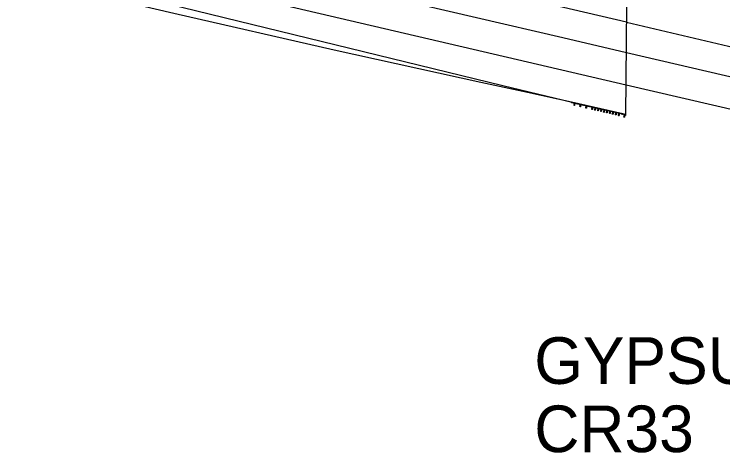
# Model space of a CAD drawing. Extents: x 1855721 to 1876784, y 662259 to 674089.
# Drawn here: x 1866661.7 to 1866935, y 670573.2 to 670742.4 of the extents above; entities that cross this region are included whole.
import ezdxf

# ---------------------------------------------------------------- set-up
doc = ezdxf.new("R2010")
doc.units = 0
for name, color, linetype in [('_CIVIL_CONSTRUCTION', 7, 'Continuous'), ('GE_X_Alignment_100_Bearings', 7, 'Continuous'), ('GE_X_Alignment_100_Curve_Data', 7, 'Continuous'), ('RD_P_GR_Lt', 7, 'Continuous'), ('SC_Scratch1', 7, 'Continuous'), ('ST_Details', 7, 'Continuous')]:
    doc.layers.add(name, color=color, linetype=linetype)

msp = doc.modelspace()

# ---------------------------------------------------------------- linework, layer by layer
at = {"layer": '_CIVIL_CONSTRUCTION'}
msp.add_line((1866897.85, 670745.57), (1866897.46, 670703.32), dxfattribs=at)
msp.add_lwpolyline([(1861013.57, 672092.03), (1861415.75, 671997.75), (1861745.02, 671920.85), (1861896.09, 671885.62), (1862012.27, 671858.53), (1862412.28, 671765.18), (1862742.48, 671687.92), (1862966.47, 671635.34), (1863245.1, 671569.98), (1863477.55, 671515.73), (1863735.03, 671455.32), (1863965.71, 671401.1), (1864326.72, 671316.71), (1864597.34, 671253.4), (1865050.25, 671147.36), (1865653.59, 671006.7), (1866010.66, 670923.03), (1866378.51, 670836.48), (1866645.32, 670774.11), (1866897.69, 670715.1)], dxfattribs=at)
at = {"layer": 'GE_X_Alignment_100_Bearings'}
msp.add_lwpolyline([(1861015.79, 672104.14), (1861503.86, 671989.83), (1862002.3, 671873.34), (1862414.38, 671777.36), (1862607.45, 671732.41), (1862665.93, 671718.29), (1862877.58, 671669), (1863214.23, 671589.72), (1863466.96, 671530.76), (1863729.81, 671469.09), (1863993.06, 671407.41), (1864487.85, 671291.8), (1864979.89, 671176.39), (1865473.4, 671061.63), (1866013.64, 670934.86), (1866351.37, 670855.59), (1866552.5, 670808.76), (1866760.09, 670759.75), (1866873.31, 670733.34), (1866897.79, 670727.56), (1867013.17, 670700.87)], dxfattribs=at)
at = {"layer": 'GE_X_Alignment_100_Curve_Data'}
for p, q in [((1866897.79, 670739.26), (1867013.1, 670712.33)), ((1866897.69, 670715.1), (1867012.95, 670688.28))]:
    msp.add_line(p, q, dxfattribs=at)
msp.add_lwpolyline([(1866897.79, 670739.26), (1866770.4, 670769.26), (1866633.99, 670801.24), (1866314.99, 670876.12), (1866186.79, 670906.2), (1865771.3, 671003.48), (1865284.25, 671117.24), (1864960.57, 671192.76), (1864427.03, 671317.77), (1864078.73, 671399.21), (1863649.61, 671499.8), (1863334.6, 671573.5), (1862712.87, 671719.11), (1862434.48, 671784.11), (1861947.09, 671897.98), (1861710.56, 671953.19), (1861378.66, 672030.79), (1861046.07, 672108.75)], dxfattribs=at)
at = {"layer": 'RD_P_GR_Lt'}
msp.add_lwpolyline([(1866876.69, 670708.41), (1866859.66, 670712.16), (1866841.64, 670716.05), (1866785.04, 670728.5), (1866723.29, 670742.62), (1866648.5, 670760.18), (1866499.74, 670794.82), (1866250.04, 670854.29), (1866058.6, 670899.37)], dxfattribs=at)
at = {"layer": 'SC_Scratch1'}
msp.add_lwpolyline([(1866897.42, 670703.5), (1866883.77, 670706.63), (1866850.17, 670714.75), (1866715.74, 670747.46), (1866529.4, 670790.93), (1866335.12, 670836.62), (1866154.72, 670878.95), (1865908, 670936.81), (1865807.98, 670960.25), (1865622.8, 671003.65), (1865282.61, 671083.17), (1864786.67, 671198.92), (1864250.64, 671324.25), (1863882.8, 671410.43), (1863380.3, 671528.31), (1862865.34, 671648.88), (1862542.41, 671724.73), (1862131.5, 671820.55), (1861446.39, 671980.7), (1861012.14, 672082.41)], dxfattribs=at)
at = {"layer": 'ST_Details'}
for p, q in [((1866897.49, 670703.49), (1866876.64, 670708.2)), ((1866896.48, 670703.93), (1866876.69, 670708.41)), ((1866877.49, 670708.23), (1866877.44, 670708.02)), ((1866877.65, 670707.97), (1866877.48, 670707.24)), ((1866877.51, 670707.23), (1866877.49, 670707.23)), ((1866877.52, 670707.24), (1866877.51, 670707.23)), ((1866877.78, 670707.18), (1866877.52, 670707.24)), ((1866877.97, 670707.9), (1866877.65, 670707.97)), ((1866877.66, 670707.2), (1866877.66, 670707.19)), ((1866877.78, 670707.16), (1866877.66, 670707.19)), ((1866877.68, 670707.11), (1866877.7, 670707.2)), ((1866877.68, 670707.18), (1866877.68, 670707.14)), ((1866877.74, 670707.12), (1866877.68, 670707.13)), ((1866877.73, 670707.1), (1866877.68, 670707.11)), ((1866877.86, 670707.93), (1866877.7, 670707.2)), ((1866877.73, 670707.1), (1866877.75, 670707.19)), ((1866877.91, 670707.92), (1866877.75, 670707.19)), ((1866877.76, 670707.16), (1866877.75, 670707.13)), ((1866877.78, 670707.18), (1866877.78, 670707.17)), ((1866877.78, 670707.17), (1866877.78, 670707.16)), ((1866877.81, 670707.16), (1866877.78, 670707.17)), ((1866877.98, 670707.89), (1866877.82, 670707.17)), ((1866878.25, 670708.05), (1866878.2, 670707.85)), ((1866879.93, 670707.45), (1866879.77, 670706.72)), ((1866879.8, 670706.71), (1866879.77, 670706.71)), ((1866879.8, 670706.73), (1866879.8, 670706.71)), ((1866880.07, 670706.67), (1866879.8, 670706.73)), ((1866880.26, 670707.38), (1866879.94, 670707.46)), ((1866879.95, 670706.68), (1866879.95, 670706.67)), ((1866880.06, 670706.64), (1866879.95, 670706.67)), ((1866879.97, 670706.66), (1866879.96, 670706.63)), ((1866879.97, 670706.59), (1866879.99, 670706.68)), ((1866880.02, 670706.6), (1866879.97, 670706.62)), ((1866880.01, 670706.58), (1866879.97, 670706.59)), ((1866880.15, 670707.41), (1866879.99, 670706.68)), ((1866880.01, 670706.58), (1866880.03, 670706.67)), ((1866880.2, 670707.4), (1866880.03, 670706.67)), ((1866880.04, 670706.65), (1866880.03, 670706.61)), ((1866880.07, 670706.67), (1866880.06, 670706.65)), ((1866880.06, 670706.65), (1866880.06, 670706.64)), ((1866880.09, 670706.64), (1866880.06, 670706.65)), ((1866880.27, 670707.37), (1866880.1, 670706.65)), ((1866882.07, 670707.19), (1866882.03, 670706.98)), ((1866882.22, 670706.93), (1866882.05, 670706.21)), ((1866882.09, 670706.19), (1866882.06, 670706.2)), ((1866882.09, 670706.21), (1866882.09, 670706.19)), ((1866882.35, 670706.15), (1866882.09, 670706.21)), ((1866882.55, 670706.87), (1866882.23, 670706.94)), ((1866882.24, 670706.16), (1866882.23, 670706.15)), ((1866882.35, 670706.13), (1866882.23, 670706.15)), ((1866882.25, 670706.08), (1866882.27, 670706.17)), ((1866882.44, 670706.89), (1866882.27, 670706.17)), ((1866882.3, 670706.07), (1866882.32, 670706.16)), ((1866882.48, 670706.88), (1866882.32, 670706.16)), ((1866882.55, 670706.86), (1866882.39, 670706.13)), ((1866882.84, 670707.02), (1866882.79, 670706.81)), ((1866884.5, 670706.42), (1866884.34, 670705.69)), ((1866884.83, 670706.35), (1866884.51, 670706.42)), ((1866884.72, 670706.37), (1866884.56, 670705.65)), ((1866884.77, 670706.36), (1866884.6, 670705.64)), ((1866884.84, 670706.34), (1866884.67, 670705.61)), ((1866885.65, 670706.16), (1866885.48, 670705.43)), ((1866885.98, 670706.09), (1866885.66, 670706.16)), ((1866886.59, 670705.95), (1866886.64, 670706.16)), ((1866882.26, 670706.15), (1866882.25, 670706.11)), ((1866882.31, 670706.09), (1866882.25, 670706.1)), ((1866882.3, 670706.07), (1866882.25, 670706.08)), ((1866882.33, 670706.13), (1866882.32, 670706.09)), ((1866882.35, 670706.15), (1866882.35, 670706.13)), ((1866882.35, 670706.14), (1866882.35, 670706.13)), ((1866882.38, 670706.13), (1866882.35, 670706.13)), ((1866884.37, 670705.67), (1866884.34, 670705.68)), ((1866884.38, 670705.69), (1866884.37, 670705.67)), ((1866884.64, 670705.63), (1866884.38, 670705.69)), ((1866884.52, 670705.64), (1866884.52, 670705.63)), ((1866884.63, 670705.61), (1866884.52, 670705.63)), ((1866884.54, 670705.63), (1866884.53, 670705.59)), ((1866884.54, 670705.56), (1866884.56, 670705.65)), ((1866884.59, 670705.57), (1866884.54, 670705.58)), ((1866884.58, 670705.55), (1866884.54, 670705.56)), ((1866884.58, 670705.55), (1866884.6, 670705.64)), ((1866884.61, 670705.61), (1866884.6, 670705.58)), ((1866884.64, 670705.62), (1866884.63, 670705.61)), ((1866884.64, 670705.63), (1866884.64, 670705.61)), ((1866884.67, 670705.61), (1866884.64, 670705.61)), ((1866885.52, 670705.42), (1866885.49, 670705.42)), ((1866885.52, 670705.43), (1866885.52, 670705.42)), ((1866885.78, 670705.37), (1866885.52, 670705.43)), ((1866885.67, 670705.39), (1866885.66, 670705.38)), ((1866885.78, 670705.35), (1866885.66, 670705.38)), ((1866885.68, 670705.3), (1866885.7, 670705.39)), ((1866885.68, 670705.37), (1866885.68, 670705.33)), ((1866885.74, 670705.31), (1866885.68, 670705.32)), ((1866885.73, 670705.29), (1866885.68, 670705.3)), ((1866885.86, 670706.12), (1866885.7, 670705.39)), ((1866885.73, 670705.29), (1866885.75, 670705.38)), ((1866885.91, 670706.11), (1866885.75, 670705.38)), ((1866885.76, 670705.35), (1866885.75, 670705.32)), ((1866885.78, 670705.37), (1866885.78, 670705.36)), ((1866885.78, 670705.36), (1866885.78, 670705.35)), ((1866885.81, 670705.35), (1866885.78, 670705.36)), ((1866885.98, 670706.08), (1866885.82, 670705.35)), ((1866886.79, 670705.9), (1866886.62, 670705.17)), ((1866886.66, 670705.16), (1866886.63, 670705.16)), ((1866886.66, 670705.17), (1866886.66, 670705.16)), ((1866886.93, 670705.11), (1866886.66, 670705.17)), ((1866887.12, 670705.83), (1866886.8, 670705.9)), ((1866886.81, 670705.13), (1866886.81, 670705.12)), ((1866886.92, 670705.09), (1866886.81, 670705.12)), ((1866886.82, 670705.04), (1866886.84, 670705.13)), ((1866886.83, 670705.11), (1866886.82, 670705.08)), ((1866886.88, 670705.05), (1866886.82, 670705.06)), ((1866886.87, 670705.03), (1866886.82, 670705.04)), ((1866887.01, 670705.86), (1866886.84, 670705.13)), ((1866886.87, 670705.03), (1866886.89, 670705.12)), ((1866887.05, 670705.85), (1866886.89, 670705.12)), ((1866886.9, 670705.1), (1866886.89, 670705.06)), ((1866886.93, 670705.11), (1866886.92, 670705.1)), ((1866886.92, 670705.1), (1866886.92, 670705.09)), ((1866886.95, 670705.09), (1866886.92, 670705.1)), ((1866887.12, 670705.82), (1866886.96, 670705.1)), ((1866887.32, 670705.79), (1866887.37, 670705.99)), ((1866887.93, 670705.64), (1866887.77, 670704.91)), ((1866887.8, 670704.9), (1866887.77, 670704.9)), ((1866887.81, 670704.92), (1866887.8, 670704.9)), ((1866888.07, 670704.86), (1866887.81, 670704.92)), ((1866888.26, 670705.57), (1866887.94, 670705.65)), ((1866887.95, 670704.87), (1866887.95, 670704.86)), ((1866888.06, 670704.83), (1866887.95, 670704.86)), ((1866887.97, 670704.85), (1866887.96, 670704.82)), ((1866887.97, 670704.78), (1866887.99, 670704.87)), ((1866888.02, 670704.79), (1866887.97, 670704.81)), ((1866888.01, 670704.77), (1866887.97, 670704.78)), ((1866888.15, 670705.6), (1866887.99, 670704.87)), ((1866888.01, 670704.77), (1866888.03, 670704.86)), ((1866888.2, 670705.59), (1866888.03, 670704.86)), ((1866888.04, 670704.84), (1866888.03, 670704.8)), ((1866888.07, 670704.84), (1866888.06, 670704.83)), ((1866888.07, 670704.86), (1866888.07, 670704.84)), ((1866888.09, 670704.83), (1866888.07, 670704.84)), ((1866888.27, 670705.56), (1866888.1, 670704.84)), ((1866889.08, 670705.38), (1866888.91, 670704.66)), ((1866888.94, 670704.64), (1866888.92, 670704.65)), ((1866888.95, 670704.66), (1866888.94, 670704.64)), ((1866889.21, 670704.6), (1866888.95, 670704.66)), ((1866889.4, 670705.31), (1866889.08, 670705.39)), ((1866889.09, 670704.61), (1866889.09, 670704.6)), ((1866889.21, 670704.57), (1866889.09, 670704.6)), ((1866889.11, 670704.59), (1866889.1, 670704.56)), ((1866889.11, 670704.52), (1866889.13, 670704.62)), ((1866889.17, 670704.53), (1866889.11, 670704.55)), ((1866889.16, 670704.51), (1866889.11, 670704.52)), ((1866889.29, 670705.34), (1866889.13, 670704.62)), ((1866889.16, 670704.51), (1866889.18, 670704.61)), ((1866889.34, 670705.33), (1866889.18, 670704.61)), ((1866889.18, 670704.58), (1866889.18, 670704.54)), ((1866889.21, 670704.6), (1866889.21, 670704.58)), ((1866889.21, 670704.58), (1866889.21, 670704.57)), ((1866889.24, 670704.57), (1866889.21, 670704.58)), ((1866889.41, 670705.31), (1866889.25, 670704.58)), ((1866890.22, 670705.12), (1866890.05, 670704.4)), ((1866890.09, 670704.38), (1866890.06, 670704.39)), ((1866890.09, 670704.4), (1866890.09, 670704.38)), ((1866890.36, 670704.34), (1866890.09, 670704.4)), ((1866890.55, 670705.06), (1866890.23, 670705.13)), ((1866890.24, 670704.35), (1866890.23, 670704.34)), ((1866890.35, 670704.31), (1866890.23, 670704.34)), ((1866890.25, 670704.27), (1866890.27, 670704.36)), ((1866890.26, 670704.34), (1866890.25, 670704.3)), ((1866890.31, 670704.28), (1866890.25, 670704.29)), ((1866890.3, 670704.26), (1866890.25, 670704.27)), ((1866890.44, 670705.08), (1866890.27, 670704.36)), ((1866890.3, 670704.26), (1866890.32, 670704.35)), ((1866890.48, 670705.07), (1866890.32, 670704.35)), ((1866890.33, 670704.32), (1866890.32, 670704.28)), ((1866890.36, 670704.34), (1866890.35, 670704.32)), ((1866890.35, 670704.33), (1866890.35, 670704.31)), ((1866890.38, 670704.31), (1866890.35, 670704.32)), ((1866890.55, 670705.05), (1866890.39, 670704.32)), ((1866891.36, 670704.86), (1866891.2, 670704.14)), ((1866891.23, 670704.12), (1866891.2, 670704.13)), ((1866891.23, 670704.14), (1866891.23, 670704.12)), ((1866891.5, 670704.08), (1866891.23, 670704.14)), ((1866891.69, 670704.8), (1866891.37, 670704.87)), ((1866891.38, 670704.09), (1866891.38, 670704.08)), ((1866891.49, 670704.06), (1866891.38, 670704.08)), ((1866891.4, 670704.08), (1866891.39, 670704.04)), ((1866891.4, 670704.01), (1866891.42, 670704.1)), ((1866891.45, 670704.02), (1866891.4, 670704.03)), ((1866891.44, 670704), (1866891.4, 670704.01)), ((1866891.58, 670704.82), (1866891.42, 670704.1)), ((1866891.44, 670704), (1866891.46, 670704.09)), ((1866891.63, 670704.81), (1866891.46, 670704.09)), ((1866891.47, 670704.06), (1866891.46, 670704.02)), ((1866891.5, 670704.08), (1866891.49, 670704.06)), ((1866891.49, 670704.07), (1866891.49, 670704.06)), ((1866891.52, 670704.06), (1866891.49, 670704.06)), ((1866891.7, 670704.79), (1866891.53, 670704.06)), ((1866892.5, 670704.61), (1866892.34, 670703.88)), ((1866892.37, 670703.86), (1866892.35, 670703.87)), ((1866892.38, 670703.88), (1866892.37, 670703.86)), ((1866892.64, 670703.82), (1866892.38, 670703.88)), ((1866892.83, 670704.54), (1866892.51, 670704.61)), ((1866892.52, 670703.83), (1866892.52, 670703.82)), ((1866892.63, 670703.8), (1866892.52, 670703.82)), ((1866892.54, 670703.82), (1866892.53, 670703.78)), ((1866892.54, 670703.75), (1866892.56, 670703.84)), ((1866892.6, 670703.76), (1866892.54, 670703.77)), ((1866892.58, 670703.74), (1866892.54, 670703.75)), ((1866892.72, 670704.56), (1866892.56, 670703.84)), ((1866892.58, 670703.74), (1866892.6, 670703.83)), ((1866892.77, 670704.55), (1866892.6, 670703.83)), ((1866892.61, 670703.8), (1866892.61, 670703.77)), ((1866892.64, 670703.81), (1866892.63, 670703.8)), ((1866892.64, 670703.82), (1866892.64, 670703.8)), ((1866892.67, 670703.8), (1866892.64, 670703.8)), ((1866892.84, 670704.53), (1866892.68, 670703.8)), ((1866893.65, 670704.35), (1866893.48, 670703.62)), ((1866893.52, 670703.61), (1866893.49, 670703.61)), ((1866893.52, 670703.62), (1866893.52, 670703.61)), ((1866893.78, 670703.56), (1866893.52, 670703.62)), ((1866893.98, 670704.28), (1866893.66, 670704.35)), ((1866893.67, 670703.58), (1866893.66, 670703.57)), ((1866893.78, 670703.54), (1866893.66, 670703.57)), ((1866893.68, 670703.49), (1866893.7, 670703.58)), ((1866893.69, 670703.56), (1866893.68, 670703.52)), ((1866893.74, 670703.5), (1866893.68, 670703.51)), ((1866893.73, 670703.48), (1866893.68, 670703.49)), ((1866893.87, 670704.31), (1866893.7, 670703.58)), ((1866893.73, 670703.48), (1866893.75, 670703.57)), ((1866893.91, 670704.29), (1866893.75, 670703.57)), ((1866893.76, 670703.54), (1866893.75, 670703.51)), ((1866893.78, 670703.56), (1866893.78, 670703.55)), ((1866893.78, 670703.55), (1866893.78, 670703.54)), ((1866893.81, 670703.54), (1866893.78, 670703.55)), ((1866893.98, 670704.27), (1866893.82, 670703.54)), ((1866894.79, 670704.09), (1866894.63, 670703.36)), ((1866895.12, 670704.02), (1866894.8, 670704.09)), ((1866895.01, 670704.05), (1866894.85, 670703.32)), ((1866895.05, 670704.04), (1866894.89, 670703.31)), ((1866895.13, 670704.01), (1866894.96, 670703.29)), ((1866895.66, 670703.9), (1866895.71, 670704.1)), ((1866895.75, 670704.09), (1866895.71, 670703.89)), ((1866896.48, 670703.71), (1866896.53, 670703.92)), ((1866896.86, 670702.69), (1866897.06, 670703.58)), ((1866896.92, 670702.68), (1866897.13, 670703.57)), ((1866897.09, 670702.64), (1866897.29, 670703.53)), ((1866897.16, 670702.62), (1866897.36, 670703.51)), ((1866897.49, 670703.49), (1866897.38, 670703.52)), ((1866897.42, 670703.5), (1866897.42, 670703.51)), ((1866897.42, 670703.5), (1866897.42, 670703.5)), ((1866894.66, 670703.35), (1866894.63, 670703.35)), ((1866894.66, 670703.36), (1866894.66, 670703.35)), ((1866894.93, 670703.3), (1866894.66, 670703.36)), ((1866894.81, 670703.32), (1866894.81, 670703.31)), ((1866894.92, 670703.28), (1866894.81, 670703.31)), ((1866894.82, 670703.23), (1866894.85, 670703.32)), ((1866894.83, 670703.3), (1866894.82, 670703.27)), ((1866894.88, 670703.24), (1866894.82, 670703.25)), ((1866894.87, 670703.22), (1866894.82, 670703.23)), ((1866894.87, 670703.22), (1866894.89, 670703.31)), ((1866894.9, 670703.29), (1866894.89, 670703.25)), ((1866894.93, 670703.3), (1866894.92, 670703.29)), ((1866894.92, 670703.29), (1866894.92, 670703.28)), ((1866894.95, 670703.28), (1866894.92, 670703.29)), ((1866897.16, 670702.62), (1866896.86, 670702.69))]:
    msp.add_line(p, q, dxfattribs=at)
for points in [[(1866876.64, 670708.2), (1866876.65, 670708.28), (1866876.65, 670708.28), (1866876.69, 670708.41)], [(1866897.14, 670703.56), (1866897.16, 670703.62), (1866897.05, 670703.64), (1866897.04, 670703.59)], [(1866897.38, 670703.52), (1866897.39, 670703.56), (1866897.29, 670703.59), (1866897.28, 670703.54)]]:
    msp.add_lwpolyline(points, dxfattribs=at)
for centre, radius, start, end in [((1866877.49, 670707.24), 0.0075, 167.2516, 257.2516), ((1866877.65, 670707.97), 0.0075, 77.2516, 167.2516), ((1866877.81, 670707.17), 0.0075, 257.2516, 347.2516), ((1866877.97, 670707.89), 0.0075, 347.2516, 77.2516), ((1866879.77, 670706.72), 0.0075, 167.2516, 257.2516), ((1866879.94, 670707.45), 0.0075, 77.2516, 167.2516), ((1866880.09, 670706.65), 0.0075, 257.2516, 347.2516), ((1866880.26, 670707.38), 0.0075, 347.2516, 77.2516), ((1866882.06, 670706.2), 0.0075, 167.2516, 257.2516), ((1866882.22, 670706.93), 0.0075, 77.2516, 167.2516), ((1866882.55, 670706.86), 0.0075, 347.2516, 77.2516), ((1866884.51, 670706.41), 0.0075, 77.2516, 167.2516), ((1866884.83, 670706.34), 0.0075, 347.2516, 77.2516), ((1866885.65, 670706.16), 0.0075, 77.2516, 167.2516), ((1866882.38, 670706.13), 0.0075, 257.2516, 347.2516), ((1866884.35, 670705.69), 0.0075, 167.2516, 257.2516), ((1866884.67, 670705.62), 0.0075, 257.2516, 347.2516), ((1866885.49, 670705.43), 0.0075, 167.2516, 257.2516), ((1866885.81, 670705.36), 0.0075, 257.2516, 347.2516), ((1866885.97, 670706.08), 0.0075, 347.2516, 77.2516), ((1866886.63, 670705.17), 0.0075, 167.2516, 257.2516), ((1866886.8, 670705.9), 0.0075, 77.2516, 167.2516), ((1866886.95, 670705.1), 0.0075, 257.2516, 347.2516), ((1866887.12, 670705.82), 0.0075, 347.2516, 77.2516), ((1866887.78, 670704.91), 0.0075, 167.2516, 257.2516), ((1866887.94, 670705.64), 0.0075, 77.2516, 167.2516), ((1866888.1, 670704.84), 0.0075, 257.2516, 347.2516), ((1866888.26, 670705.57), 0.0075, 347.2516, 77.2516), ((1866888.92, 670704.65), 0.0075, 167.2516, 257.2516), ((1866889.08, 670705.38), 0.0075, 77.2516, 167.2516), ((1866889.24, 670704.58), 0.0075, 257.2516, 347.2516), ((1866889.4, 670705.31), 0.0075, 347.2516, 77.2516), ((1866890.06, 670704.39), 0.0075, 167.2516, 257.2516), ((1866890.23, 670705.12), 0.0075, 77.2516, 167.2516), ((1866890.38, 670704.32), 0.0075, 257.2516, 347.2516), ((1866890.55, 670705.05), 0.0075, 347.2516, 77.2516), ((1866891.2, 670704.14), 0.0075, 167.2516, 257.2516), ((1866891.37, 670704.86), 0.0075, 77.2516, 167.2516), ((1866891.52, 670704.06), 0.0075, 257.2516, 347.2516), ((1866891.69, 670704.79), 0.0075, 347.2516, 77.2516), ((1866892.35, 670703.88), 0.0075, 167.2516, 257.2516), ((1866892.51, 670704.6), 0.0075, 77.2516, 167.2516), ((1866892.67, 670703.81), 0.0075, 257.2516, 347.2516), ((1866892.83, 670704.53), 0.0075, 347.2516, 77.2516), ((1866893.49, 670703.62), 0.0075, 167.2516, 257.2516), ((1866893.65, 670704.35), 0.0075, 77.2516, 167.2516), ((1866893.81, 670703.55), 0.0075, 257.2516, 347.2516), ((1866893.98, 670704.27), 0.0075, 347.2516, 77.2516), ((1866894.8, 670704.09), 0.0075, 77.2516, 167.2516), ((1866895.12, 670704.01), 0.0075, 347.2516, 77.2516), ((1866896.26, 670702.59), 1.36, 45.2966, 80.3734), ((1866894.63, 670703.36), 0.0075, 167.2516, 257.2516), ((1866894.95, 670703.29), 0.0075, 257.2516, 347.2516)]:
    msp.add_arc(centre, radius, start, end, dxfattribs=at)
for centre, major_axis, ratio in [((1866877.6, 670708.11), (-0.0562, 0.0127), 0.423485), ((1866878.11, 670707.98), (-0.0562, 0.0127), 0.423485), ((1866882.19, 670707.07), (-0.0562, 0.0127), 0.423485), ((1866882.7, 670706.94), (-0.0562, 0.0127), 0.423485), ((1866886.72, 670706.04), (-0.0562, 0.0127), 0.423485), ((1866887.23, 670705.91), (-0.0562, 0.0127), 0.423485), ((1866895.87, 670703.97), (-0.0562, 0.0127), 0.423485), ((1866896.39, 670703.84), (-0.0607, 0.0137), 0.392116)]:
    msp.add_ellipse(centre, major_axis=major_axis, ratio=ratio, dxfattribs=at)
for centre, major_axis, ratio, start_param, end_param in [((1866877.68, 670707.14), (0.0023, 0.0102), 0.929688, 1.586202, 2.897406), ((1866877.74, 670707.13), (0.0023, 0.0102), 0.929688, 3.345604, 4.722982), ((1866877.89, 670707.92), (-0.0762, 0.0172), 0.312583, 3.061844, 6.362934), ((1866879.97, 670706.63), (0.0023, 0.0102), 0.929688, 1.586202, 2.897406), ((1866880.02, 670706.61), (0.0023, 0.0102), 0.929688, 3.345604, 4.722982), ((1866880.17, 670707.41), (-0.0762, 0.0172), 0.312583, 3.061844, 6.362934), ((1866882.46, 670706.89), (-0.0762, 0.0172), 0.312583, 3.061844, 6.362934), ((1866884.75, 670706.37), (-0.0762, 0.0172), 0.312583, 3.061844, 6.362934), ((1866882.26, 670706.11), (0.0023, 0.0102), 0.929688, 1.586202, 2.897406), ((1866882.31, 670706.1), (0.0023, 0.0102), 0.929688, 3.345604, 4.722982), ((1866884.54, 670705.59), (0.0023, 0.0102), 0.929688, 1.586202, 2.897406), ((1866884.6, 670705.58), (0.0023, 0.0102), 0.929688, 3.345604, 4.722982), ((1866885.69, 670705.33), (0.0023, 0.0102), 0.929688, 1.586202, 2.897406), ((1866885.74, 670705.32), (0.0023, 0.0102), 0.929688, 3.345604, 4.722982), ((1866885.89, 670706.11), (-0.0762, 0.0172), 0.312583, 3.061844, 6.362934), ((1866886.83, 670705.07), (0.0023, 0.0102), 0.929688, 1.586202, 2.897406), ((1866886.88, 670705.06), (0.0023, 0.0102), 0.929688, 3.345604, 4.722982), ((1866887.03, 670705.85), (-0.0762, 0.0172), 0.312583, 3.061844, 6.362934), ((1866887.97, 670704.82), (0.0023, 0.0102), 0.929688, 1.586202, 2.897406), ((1866888.02, 670704.8), (0.0023, 0.0102), 0.929688, 3.345604, 4.722982), ((1866888.17, 670705.59), (-0.0762, 0.0172), 0.312583, 3.061844, 6.362934), ((1866889.11, 670704.56), (0.0023, 0.0102), 0.929688, 1.586202, 2.897406), ((1866889.17, 670704.54), (0.0023, 0.0102), 0.929688, 3.345604, 4.722982), ((1866890.26, 670704.3), (0.0023, 0.0102), 0.929688, 1.586202, 2.897406), ((1866890.31, 670704.29), (0.0023, 0.0102), 0.929688, 3.345604, 4.722982), ((1866891.4, 670704.04), (0.0023, 0.0102), 0.929688, 1.586202, 2.897406), ((1866891.45, 670704.03), (0.0023, 0.0102), 0.929688, 3.345604, 4.722982), ((1866892.54, 670703.78), (0.0023, 0.0102), 0.929688, 1.586202, 2.897406), ((1866892.6, 670703.77), (0.0023, 0.0102), 0.929688, 3.345604, 4.722982), ((1866893.69, 670703.52), (0.0023, 0.0102), 0.929688, 1.586202, 2.897406), ((1866893.74, 670703.51), (0.0023, 0.0102), 0.929688, 3.345604, 4.722982), ((1866896.1, 670703.8), (-0.0762, 0.0172), 0.312583, 3.061844, 6.362934), ((1866894.83, 670703.26), (0.0023, 0.0102), 0.929688, 1.586202, 2.897406), ((1866894.88, 670703.25), (0.0023, 0.0102), 0.929688, 3.345604, 4.722982)]:
    msp.add_ellipse(centre, major_axis=major_axis, ratio=ratio, start_param=start_param, end_param=end_param, dxfattribs=at)

# ---------------------------------------------------------------- texts
at = {"layer": 'SC_Scratch1'}
for s, p in [('GYPSUM RD.', (1866862.29, 670599.76)), ('CR33', (1866862.29, 670573.43))]:
    msp.add_text(s, height=18, dxfattribs=at).set_placement(p)

doc.saveas('drawing.dxf')
